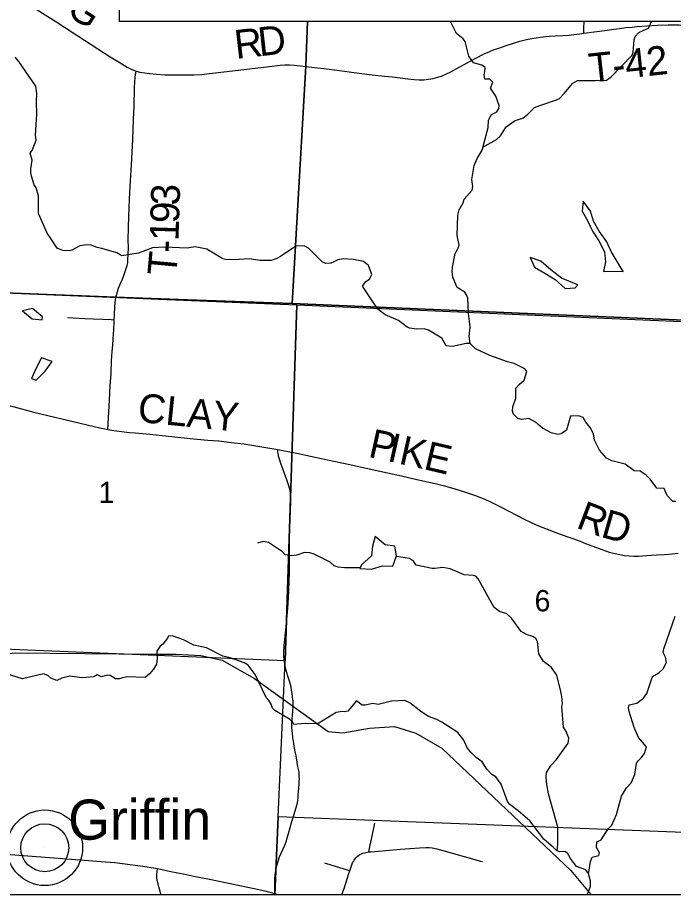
# Model space of a CAD drawing. Extents: x 0 to 34, y 0 to 22.
# Drawn here: x 4.911 to 6.203, y 14.1 to 15.827 of the extents above; entities that cross this region are included whole.
import ezdxf

# ---------------------------------------------------------------- set-up
doc = ezdxf.new("R2010")
doc.units = 0
for name, color, linetype in [('Default', 7, 'Continuous'), ('GM_X_County_Road', 7, 'Continuous'), ('GM_X_County_Road_Text', 7, 'Continuous'), ('GM_X_Minor_Lake', 7, 'Continuous'), ('GM_X_Minor_River', 7, 'Continuous'), ('GM_X_Rail_Line', 7, 'Continuous'), ('GM_X_Section', 7, 'Continuous'), ('GM_X_Section_Text', 7, 'Continuous'), ('GM_X_State_Route', 7, 'Continuous'), ('GM_X_Township_Road', 7, 'Continuous'), ('GM_X_Township_Road_Text', 7, 'Continuous'), ('GM_X_Unincorporated', 7, 'Continuous'), ('GM_X_Unincorporated_Location', 7, 'Continuous'), ('GM_X_Unincorporated_Text', 7, 'Continuous'), ('SH_Data', 7, 'Continuous')]:
    doc.layers.add(name, color=color, linetype=linetype)

msp = doc.modelspace()

# ---------------------------------------------------------------- linework, layer by layer
at = {"layer": 'Default'}
msp.add_lwpolyline([(5.112, 16.1987), (6.6303, 16.1987), (6.6303, 15.8189), (5.112, 15.8189)], close=True, dxfattribs=at)
at = {"layer": 'GM_X_County_Road'}
msp.add_line((5.4173, 14.1), (5.4174, 14.1019), dxfattribs=at)
for points in [[(4.9482, 15.8434), (4.9887, 15.8174), (5.0038, 15.808), (5.019, 15.7979), (5.0432, 15.782), (5.0691, 15.765), (5.0933, 15.7496), (5.1112, 15.7388), (5.1271, 15.7288), (5.1365, 15.7241), (5.1416, 15.7224), (5.1447, 15.7214)], [(6.0265, 15.7958), (6.0265, 15.806), (6.0268, 15.8189)], [(5.4792, 15.7304), (5.4958, 15.7284), (5.5019, 15.7276), (5.5142, 15.7261), (5.5449, 15.7225), (5.5786, 15.718), (5.6093, 15.7142), (5.6339, 15.7114), (5.6493, 15.7097), (5.68, 15.7058), (5.6924, 15.7046), (5.7017, 15.7041), (5.711, 15.7043), (5.7203, 15.7053), (5.7295, 15.707), (5.7386, 15.7092), (5.7474, 15.7121), (5.756, 15.7156), (5.7644, 15.7198), (5.7806, 15.729), (5.8134, 15.7465), (5.83, 15.755), (5.8412, 15.7601), (5.8498, 15.7636), (5.8586, 15.7667), (5.8732, 15.7715), (5.8879, 15.7761), (5.9, 15.7799), (5.9132, 15.7832), (5.9235, 15.7854), (5.9321, 15.7869), (5.941, 15.7881), (5.9515, 15.7895), (5.9577, 15.7902), (5.9698, 15.7908), (5.9849, 15.7915), (5.9973, 15.7922), (6.0066, 15.7932), (6.0184, 15.7945), (6.0265, 15.7958)], [(5.1447, 15.7214), (5.1521, 15.7195), (5.162, 15.7179), (5.1708, 15.7168), (5.1846, 15.7152), (5.2013, 15.7141), (5.2178, 15.7136), (5.2399, 15.7138), (5.2585, 15.7141), (5.274, 15.7148), (5.2895, 15.7163), (5.3172, 15.7197), (5.3789, 15.7268), (5.4066, 15.7303), (5.4281, 15.7329), (5.4374, 15.7335), (5.4466, 15.7335), (5.4558, 15.733), (5.4681, 15.7318), (5.4792, 15.7304)], [(4.878, 15.0668), (4.9044, 15.0599), (4.9435, 15.0498), (4.9706, 15.0431), (5.0099, 15.0338), (5.0734, 15.019), (5.0828, 15.017), (5.0888, 15.0157)], [(5.0888, 15.0157), (5.1008, 15.0138), (5.1319, 15.0098), (5.1428, 15.0087), (5.1717, 15.0062), (5.1902, 15.0046), (5.2211, 15.0014), (5.2511, 14.9979), (5.2859, 14.9946), (5.3066, 14.9929)], [(5.3066, 14.9929), (5.3076, 14.9929), (5.3323, 14.9902), (5.3569, 14.9871), (5.3845, 14.983), (5.4121, 14.9784), (5.4235, 14.9763)], [(5.4174, 14.1019), (5.4175, 14.1033), (5.418, 14.1303), (5.4185, 14.1381), (5.4197, 14.1469), (5.4217, 14.1562), (5.4242, 14.1653), (5.4273, 14.1741), (5.4309, 14.1827), (5.4372, 14.1969), (5.4405, 14.2055), (5.4424, 14.2113), (5.4448, 14.2201), (5.4478, 14.2319), (5.4512, 14.2435), (5.456, 14.2578), (5.4592, 14.2694), (5.4619, 14.2779), (5.463, 14.2841), (5.4637, 14.2908), (5.464, 14.2958), (5.4642, 14.3025), (5.4648, 14.3096), (5.4655, 14.3168), (5.466, 14.3232), (5.4662, 14.3277), (5.466, 14.3322), (5.4654, 14.341), (5.4641, 14.3465), (5.4635, 14.3491), (5.4629, 14.3518), (5.4617, 14.3606), (5.4595, 14.3729), (5.4573, 14.3843), (5.4552, 14.3969), (5.4534, 14.4091), (5.4525, 14.4177), (5.4514, 14.4273), (5.4516, 14.4371), (5.4526, 14.4525), (5.4532, 14.4617), (5.4537, 14.4704), (5.4537, 14.4749), (5.4537, 14.4814), (5.4534, 14.4834), (5.4517, 14.4956), (5.4509, 14.502), (5.4498, 14.5081), (5.4491, 14.5112), (5.4467, 14.52), (5.4449, 14.5259), (5.443, 14.5318), (5.4421, 14.5347), (5.4404, 14.5407), (5.4382, 14.5497), (5.4366, 14.5589), (5.4358, 14.5682), (5.4357, 14.5775), (5.4363, 14.5899), (5.4374, 14.6023), (5.44, 14.627), (5.4409, 14.6362), (5.4421, 14.6484), (5.4433, 14.6636), (5.4438, 14.6728), (5.4451, 14.6975), (5.4463, 14.7192), (5.4468, 14.7316), (5.447, 14.7409), (5.4466, 14.7718), (5.4465, 14.7843), (5.4465, 14.7936), (5.4467, 14.806), (5.447, 14.8214), (5.4474, 14.8338), (5.4484, 14.8525), (5.4495, 14.8772), (5.4494, 14.8834), (5.4488, 14.8895), (5.4478, 14.8955), (5.4455, 14.9045), (5.4416, 14.9162), (5.4298, 14.9483), (5.4269, 14.9572), (5.4253, 14.9632), (5.4248, 14.9654), (5.4242, 14.9683), (5.4238, 14.9708), (5.4235, 14.9763)], [(5.4235, 14.9763), (5.4335, 14.9745), (5.4609, 14.9687), (5.4791, 14.9648), (5.5215, 14.9558), (5.5655, 14.9465), (5.6033, 14.9379), (5.6246, 14.9335), (5.6397, 14.9302), (5.667, 14.9241), (5.6972, 14.9173), (5.7335, 14.9091), (5.7516, 14.9046), (5.7725, 14.8988), (5.7933, 14.8922), (5.8109, 14.886), (5.8312, 14.8781), (5.8425, 14.8731), (5.8649, 14.8621), (5.9089, 14.839), (5.9227, 14.8321), (5.9369, 14.8259), (5.9542, 14.819), (5.9774, 14.8103), (6.0008, 14.8021), (6.0155, 14.797), (6.0298, 14.7912), (6.0442, 14.7855), (6.0617, 14.7791), (6.0763, 14.7743), (6.0882, 14.7711), (6.0972, 14.7691), (6.1063, 14.7676), (6.1154, 14.7666), (6.1247, 14.7661), (6.1339, 14.7662), (6.1495, 14.7673), (6.1693, 14.7688), (6.1848, 14.7695), (6.2, 14.7704), (6.212, 14.7717)]]:
    msp.add_lwpolyline(points, dxfattribs=at)
at = {"layer": 'GM_X_Minor_Lake'}
for points in [[(6.1036, 15.3264), (6.0918, 15.3462), (6.0801, 15.3663), (6.0714, 15.3853), (6.0563, 15.4061), (6.0453, 15.4255), (6.0392, 15.4452), (6.0249, 15.4654), (6.0226, 15.4452), (6.0339, 15.4255), (6.043, 15.4061), (6.0559, 15.3872), (6.0669, 15.3655), (6.0691, 15.3454), (6.065, 15.3264)], [(6.1036, 15.3264), (6.0918, 15.3462), (6.0801, 15.3663), (6.0714, 15.3853), (6.0563, 15.4061), (6.0453, 15.4255), (6.0392, 15.4452), (6.0249, 15.4654), (6.0226, 15.4452), (6.0339, 15.4255), (6.043, 15.4061), (6.0559, 15.3872), (6.0669, 15.3655), (6.0691, 15.3454), (6.065, 15.3264), (6.0847, 15.3272), (6.1036, 15.3264), (6.1036, 15.3279)], [(6.0147, 15.3002), (5.9821, 15.3135), (5.9609, 15.3298), (5.9413, 15.3469), (5.9204, 15.3541), (5.9292, 15.3352)], [(6.0147, 15.3002), (5.9821, 15.3135), (5.9609, 15.3298), (5.9413, 15.3469), (5.9204, 15.3541), (5.9292, 15.3352), (5.9496, 15.3234), (5.97, 15.3109), (5.9897, 15.2934), (6.009, 15.2945), (6.0147, 15.3002)], [(5.9292, 15.3352), (5.9496, 15.3234), (5.97, 15.3109), (5.9897, 15.2934), (6.009, 15.2945), (6.0147, 15.3002)], [(6.065, 15.3264), (6.0847, 15.3272), (6.1036, 15.3264)], [(4.9603, 15.2375), (4.9409, 15.2535), (4.9208, 15.249), (4.9401, 15.2334), (4.9594, 15.2315)], [(4.9606, 15.2372), (4.9409, 15.2535), (4.9208, 15.249), (4.9401, 15.2334), (4.9594, 15.2315), (4.9602, 15.2368)], [(4.9594, 15.2315), (4.9603, 15.2375)], [(4.9587, 15.1564), (4.9473, 15.1351), (4.939, 15.1158), (4.9481, 15.1127)], [(4.9481, 15.1127), (4.9655, 15.1302), (4.9791, 15.1495), (4.9587, 15.1564), (4.9473, 15.1351), (4.939, 15.1158), (4.9481, 15.1127)], [(4.9481, 15.1127), (4.9655, 15.1302), (4.9791, 15.1495), (4.9587, 15.1564)], [(5.6541, 14.7856), (5.6348, 14.7886), (5.6152, 14.8049), (5.6103, 14.7856), (5.608, 14.7666), (5.5883, 14.7491), (5.5849, 14.7419)], [(5.5849, 14.7419), (5.6084, 14.7404), (5.6299, 14.7468), (5.6504, 14.7465), (5.6575, 14.7666), (5.6541, 14.7856), (5.6348, 14.7886), (5.6152, 14.8049), (5.6103, 14.7856), (5.608, 14.7666), (5.5883, 14.7491), (5.5849, 14.7419)], [(5.5849, 14.7419), (5.6084, 14.7404), (5.6299, 14.7468), (5.6504, 14.7465), (5.6575, 14.7666), (5.6541, 14.7856)]]:
    msp.add_lwpolyline(points, dxfattribs=at)
at = {"layer": 'GM_X_Minor_River'}
for points in [[(5.8027, 15.1852), (5.8003, 15.1992), (5.8025, 15.217), (5.7993, 15.2448), (5.7981, 15.2744), (5.7961, 15.2797), (5.7919, 15.2861), (5.7771, 15.2951), (5.7683, 15.3152), (5.7672, 15.3259), (5.7675, 15.3353), (5.773, 15.3623), (5.7783, 15.3711), (5.7805, 15.3787), (5.777, 15.3977), (5.7783, 15.4379), (5.7809, 15.4478), (5.7888, 15.4619), (5.7903, 15.4688), (5.8064, 15.4871), (5.8079, 15.4939), (5.8059, 15.508), (5.81, 15.5357), (5.8159, 15.549), (5.8257, 15.5654), (5.8376, 15.6103), (5.8382, 15.6247), (5.8442, 15.6361), (5.8548, 15.6411), (5.8589, 15.6476), (5.8597, 15.6533), (5.8531, 15.6719), (5.8425, 15.6878), (5.8473, 15.6992), (5.8409, 15.7052), (5.8314, 15.7052), (5.8302, 15.7143), (5.8313, 15.7196), (5.8317, 15.7284), (5.8256, 15.7329), (5.8089, 15.7377), (5.7998, 15.7506), (5.7924, 15.7798), (5.7883, 15.7851), (5.7757, 15.7956), (5.7681, 15.81), (5.7637, 15.8189)], [(5.8274, 15.5717), (5.854, 15.5868), (5.8619, 15.5937), (5.8735, 15.6112), (5.8912, 15.6239), (5.9059, 15.6289), (5.9161, 15.6362), (5.9289, 15.6495), (5.9395, 15.6538), (5.9727, 15.6646), (5.978, 15.6676), (5.9878, 15.6772), (6.0047, 15.6978), (6.0138, 15.7028), (6.0489, 15.703), (6.0538, 15.7034), (6.0603, 15.7023), (6.0709, 15.7031), (6.0795, 15.7092), (6.1213, 15.7527), (6.1235, 15.7588), (6.1253, 15.7831), (6.1275, 15.7896), (6.1347, 15.7976), (6.143, 15.8011), (6.1532, 15.8057), (6.1594, 15.8189)], [(5.8027, 15.1852), (5.7944, 15.1851), (5.7675, 15.1789), (5.7554, 15.1803), (5.7463, 15.1951), (5.7201, 15.2109), (5.7121, 15.2135), (5.6959, 15.2131), (5.6834, 15.2149), (5.6781, 15.2171), (5.6613, 15.2303), (5.6348, 15.2416), (5.6208, 15.2525), (5.5906, 15.2975), (5.597, 15.3067), (5.6042, 15.3117), (5.6087, 15.3208), (5.6022, 15.3386), (5.5927, 15.3466), (5.573, 15.3502), (5.5525, 15.3513), (5.542, 15.3497), (5.5337, 15.3459), (5.528, 15.3428), (5.5174, 15.3423), (5.5113, 15.3454), (5.484, 15.3729), (5.4756, 15.3771), (5.459, 15.3766), (5.4288, 15.3563), (5.4216, 15.3521), (5.4103, 15.3482), (5.3884, 15.3481), (5.3679, 15.3514), (5.3373, 15.3497), (5.3207, 15.3504), (5.3157, 15.3519), (5.2839, 15.3707), (5.2611, 15.3751), (5.2453, 15.3728), (5.2006, 15.3748), (5.1768, 15.3732), (5.1492, 15.3627), (5.1163, 15.3573), (5.1069, 15.3637), (5.0769, 15.3718), (5.0682, 15.3741), (5.0561, 15.3786), (5.0478, 15.3793), (5.0342, 15.3773), (5.0179, 15.3685), (5.0126, 15.3673), (5.0005, 15.368), (4.9892, 15.3725), (4.9766, 15.3918), (4.9693, 15.402), (4.9525, 15.441), (4.9523, 15.4756), (4.9477, 15.4915), (4.9443, 15.4972), (4.9385, 15.5146), (4.9377, 15.5215), (4.9373, 15.5291), (4.9399, 15.5458), (4.9364, 15.5594), (4.9401, 15.5651), (4.9476, 15.5853), (4.9468, 15.5952), (4.9492, 15.6362), (4.9483, 15.6613), (4.9494, 15.6772), (4.9471, 15.6916), (4.9139, 15.7404), (4.9063, 15.7487)], [(6.2072, 14.874), (6.2015, 14.874), (6.1905, 14.8853), (6.1843, 14.8993), (6.1699, 14.9), (6.1566, 14.9178), (6.149, 14.9254), (6.1372, 14.9333), (6.1255, 14.9343), (6.1077, 14.9472), (6.0812, 14.9539), (6.0709, 14.9591), (6.0568, 14.975), (6.0469, 14.9947), (6.0449, 15.0072), (6.0388, 15.0197), (6.0304, 15.0299), (6.0251, 15.0394), (6.0156, 15.0424), (5.9997, 15.0419), (5.9923, 15.0145), (5.9814, 15.0072), (5.9753, 15.0057), (5.9621, 15.009), (5.9545, 15.0128), (5.945, 15.0184), (5.931, 15.0301), (5.9177, 15.0373), (5.9033, 15.0353), (5.8961, 15.0375), (5.8878, 15.0455), (5.8855, 15.0515), (5.8865, 15.0603), (5.8921, 15.077), (5.8924, 15.0968), (5.8992, 15.1044), (5.9086, 15.1124), (5.9142, 15.1295), (5.91, 15.1348), (5.8888, 15.1457), (5.8759, 15.1487), (5.8414, 15.1611), (5.8126, 15.1746), (5.8027, 15.1852)], [(5.5854, 14.743), (5.5549, 14.7429), (5.5428, 14.7444), (5.5345, 14.7474), (5.5269, 14.7546), (5.4954, 14.7703), (5.4867, 14.7729), (5.4764, 14.7733), (5.461, 14.7679), (5.4508, 14.7667), (5.4379, 14.7689), (5.4326, 14.7749), (5.4056, 14.793), (5.395, 14.7952), (5.384, 14.7918)], [(5.9735, 14.1862), (5.9749, 14.1992), (5.9748, 14.2322), (5.9563, 14.2978), (5.9531, 14.3168), (5.9519, 14.3304), (5.953, 14.3403), (5.9617, 14.3544), (5.9722, 14.3655), (5.9955, 14.3979), (5.9966, 14.4074), (5.9916, 14.421), (5.9859, 14.4297), (5.9826, 14.4703), (5.9845, 14.4753), (5.9829, 14.4897), (5.981, 14.4999), (5.9732, 14.5318), (5.9622, 14.5477), (5.947, 14.559), (5.9378, 14.5741), (5.9347, 14.598), (5.9316, 14.6041), (5.9259, 14.6082), (5.9131, 14.6119), (5.9028, 14.618), (5.8841, 14.6441), (5.8743, 14.6528), (5.8599, 14.6572), (5.8496, 14.6652), (5.8408, 14.6803), (5.824, 14.711), (5.8183, 14.7212), (5.8134, 14.7265), (5.8081, 14.7283), (5.7906, 14.7294), (5.763, 14.7414), (5.7486, 14.7436), (5.7327, 14.7416), (5.7274, 14.7416), (5.696, 14.7482), (5.691, 14.7562), (5.683, 14.7615), (5.6571, 14.7653)], [(6.0342, 14.1428), (6.0361, 14.1441), (6.039, 14.165), (6.0424, 14.1737), (6.056, 14.1764), (6.0571, 14.1821), (6.051, 14.1924), (6.0521, 14.2038), (6.06, 14.2072), (6.0739, 14.2293), (6.081, 14.2362), (6.0908, 14.2575), (6.1004, 14.2932), (6.1105, 14.31), (6.1192, 14.3199), (6.1263, 14.3363), (6.13, 14.3587), (6.1341, 14.3637), (6.139, 14.369), (6.1458, 14.3774), (6.1495, 14.3907), (6.1339, 14.4088), (6.1251, 14.4285), (6.1155, 14.4604), (6.1143, 14.4676), (6.1154, 14.4733), (6.1305, 14.4768), (6.1437, 14.4867), (6.1505, 14.4955), (6.1613, 14.529), (6.1737, 14.5363), (6.1824, 14.5443), (6.1891, 14.5565), (6.1868, 14.5671), (6.1822, 14.5766), (6.1837, 14.5834), (6.2057, 14.6477)], [(6.0329, 14.1), (6.0348, 14.1038), (6.0393, 14.116), (6.0396, 14.1259), (6.0354, 14.141), (6.0304, 14.1486), (6.0118, 14.1553), (5.9997, 14.1708), (5.9943, 14.1811), (5.989, 14.1848), (5.9784, 14.1836), (5.9727, 14.1866), (5.9663, 14.1927), (5.9473, 14.2089), (5.9198, 14.2452), (5.897, 14.2648), (5.8803, 14.2769), (5.8758, 14.2833), (5.8635, 14.3174), (5.8532, 14.3314), (5.8449, 14.3363), (5.8353, 14.3469), (5.8262, 14.3613), (5.8144, 14.3695), (5.8034, 14.3801), (5.7966, 14.3884), (5.79, 14.4036), (5.7782, 14.4191), (5.7464, 14.4394), (5.7365, 14.4447), (5.7206, 14.4503), (5.7054, 14.4605), (5.6837, 14.4771), (5.6735, 14.4816), (5.6474, 14.4803), (5.6213, 14.4741), (5.6107, 14.4759), (5.5956, 14.4728), (5.5896, 14.4728), (5.5789, 14.4811), (5.5613, 14.4612), (5.5556, 14.4593), (5.5503, 14.46), (5.5386, 14.4581), (5.5046, 14.4374), (5.4993, 14.4362), (5.4774, 14.4369), (5.4555, 14.4348), (5.4528, 14.4398), (5.4467, 14.4454), (5.4179, 14.462), (5.4129, 14.4669), (5.4103, 14.4748), (5.4057, 14.482), (5.4007, 14.4877), (5.3793, 14.5328), (5.3652, 14.5513), (5.3573, 14.5558), (5.3296, 14.5659), (5.3156, 14.5693), (5.2833, 14.5858), (5.2583, 14.591), (5.2382, 14.6011), (5.2174, 14.6086), (5.2083, 14.6093), (5.2068, 14.6044), (5.1974, 14.5925), (5.1922, 14.5891), (5.1858, 14.5792), (5.1862, 14.5655), (5.1848, 14.5537), (5.1792, 14.5438), (5.1713, 14.5343), (5.1626, 14.527), (5.1263, 14.5288), (5.118, 14.5264), (5.1119, 14.5245), (5.104, 14.5248), (5.0937, 14.5309), (5.0884, 14.5316), (5.076, 14.5285), (5.068, 14.5322), (5.0612, 14.5284), (5.0381, 14.5268), (5.0143, 14.5297), (4.9984, 14.5262), (4.9886, 14.5216), (4.9769, 14.526), (4.9712, 14.531), (4.9621, 14.5347), (4.9209, 14.5246), (4.8898, 14.5347)]]:
    msp.add_lwpolyline(points, dxfattribs=at)
at = {"layer": 'GM_X_Rail_Line'}
for points in [[(2.1, 18.4819), (2.1, 15.4153), (3.9123, 15.3323), (3.9451, 15.3313), (3.973, 15.329), (4.0133, 15.3262), (4.0257, 15.3251), (4.0381, 15.324), (4.0782, 15.3206), (4.1061, 15.3185), (4.1743, 15.3141), (4.1849, 15.3132), (4.1956, 15.3121), (4.1973, 15.3118), (5.1044, 15.2759), (5.2458, 15.271), (5.4522, 15.2638), (5.479, 15.731), (5.4821, 15.8189)], [(5.4821, 15.8189), (5.479, 15.731), (5.4522, 15.2638), (6.2705, 15.2288), (6.4764, 15.22), (8.4272, 15.1429)], [(4.1532, 14.3849), (4.2282, 14.4236), (4.3306, 14.4812), (4.4305, 14.5219), (4.5308, 14.5414), (4.648, 14.5518), (4.9079, 14.5757), (5.1792, 14.5733), (5.2237, 14.5733), (5.272, 14.5707), (5.3144, 14.561), (5.3776, 14.525), (5.5225, 14.4206), (5.5518, 14.4183), (5.6045, 14.4272), (5.6536, 14.4306), (5.6957, 14.4175), (5.7467, 14.3883), (6.0004, 14.1469), (6.0402, 14.1)]]:
    msp.add_lwpolyline(points, dxfattribs=at)
msp.add_lwpolyline([(2.1, 15.4153), (2.1, 14.1), (6.4223, 14.1), (6.4607, 14.8895), (6.4764, 15.22), (6.2705, 15.2288), (5.4522, 15.2638), (5.2458, 15.271), (5.1044, 15.2759), (4.1973, 15.3118), (4.1956, 15.3121), (4.1849, 15.3132), (4.1743, 15.3141), (4.1061, 15.3185), (4.0782, 15.3206), (4.0381, 15.324), (4.0257, 15.3251), (4.0133, 15.3262), (3.973, 15.329), (3.9451, 15.3313), (3.9123, 15.3323)], close=True, dxfattribs=at)
at = {"layer": 'GM_X_Section'}
for points in [[(5.4613, 15.2612), (5.438, 14.5597), (4.7084, 14.5904), (4.7434, 15.2908)], [(6.4755, 15.2172), (6.4272, 14.2142), (5.4247, 14.2527), (5.438, 14.5597), (5.4613, 15.2612)]]:
    msp.add_lwpolyline(points, close=True, dxfattribs=at)
at = {"layer": 'GM_X_State_Route'}
for points in [[(4.8801, 14.1799), (5.0254, 14.1687), (5.0841, 14.1645), (5.1027, 14.1629), (5.1181, 14.161), (5.1581, 14.1554), (5.1826, 14.1517), (5.187, 14.1508), (5.213, 14.1454), (5.2404, 14.14), (5.2586, 14.1362), (5.289, 14.1298), (5.3772, 14.1115), (5.3984, 14.1068), (5.4174, 14.1019)], [(5.4174, 14.1019), (5.4225, 14.1006), (5.4249, 14.1)]]:
    msp.add_lwpolyline(points, dxfattribs=at)
at = {"layer": 'GM_X_Township_Road'}
for points in [[(6.0265, 15.7958), (6.0466, 15.7984), (6.072, 15.8019), (6.0843, 15.8036), (6.0965, 15.8054), (6.1088, 15.807), (6.1211, 15.808), (6.1303, 15.809), (6.151, 15.8106), (6.1715, 15.8118), (6.1922, 15.8123), (6.2136, 15.8121), (6.23, 15.8111), (6.2465, 15.8096), (6.2599, 15.8077), (6.2905, 15.8036), (6.3057, 15.8011), (6.3269, 15.7969), (6.345, 15.7931), (6.354, 15.7915), (6.3568, 15.7911), (6.3596, 15.7909), (6.3626, 15.7913)], [(5.1046, 15.2754), (5.1058, 15.2802), (5.1081, 15.2869), (5.1103, 15.294), (5.1134, 15.3019), (5.1176, 15.3115), (5.1209, 15.3208), (5.1245, 15.3306), (5.127, 15.3388), (5.1283, 15.344), (5.1287, 15.3504), (5.129, 15.3604), (5.1295, 15.374), (5.1293, 15.3886), (5.13, 15.4134), (5.1306, 15.4351), (5.1316, 15.4691), (5.1327, 15.4938), (5.1341, 15.5158), (5.1355, 15.537), (5.138, 15.5866), (5.1398, 15.6268), (5.1406, 15.6516), (5.1414, 15.6889), (5.1427, 15.7102), (5.1447, 15.7214)], [(5.1014, 15.2317), (5.1019, 15.2406), (5.1031, 15.2583), (5.1041, 15.2711), (5.1046, 15.2754)], [(5.0099, 15.2364), (5.0209, 15.2354), (5.044, 15.234), (5.0953, 15.232), (5.1014, 15.2317)], [(5.0888, 15.0157), (5.0923, 15.0734), (5.0939, 15.1012), (5.0953, 15.126), (5.0964, 15.1508), (5.0976, 15.1694), (5.0987, 15.1817), (5.0997, 15.1941), (5.1007, 15.2127), (5.1013, 15.2283), (5.1014, 15.2317)], [(5.6032, 14.1836), (5.6043, 14.1904), (5.6053, 14.1967), (5.6079, 14.2091), (5.6126, 14.2308), (5.6144, 14.2401)], [(5.5655, 14.1467), (5.5687, 14.1561), (5.571, 14.162), (5.5724, 14.1648), (5.574, 14.1676), (5.5758, 14.1702), (5.5777, 14.1727), (5.58, 14.175), (5.5826, 14.177), (5.5853, 14.1787), (5.5882, 14.1801), (5.5911, 14.1813), (5.5942, 14.1822), (5.5973, 14.1828), (5.6032, 14.1836)], [(5.6032, 14.1836), (5.6066, 14.184), (5.6221, 14.1853), (5.6654, 14.189), (5.6839, 14.1906), (5.7026, 14.1921), (5.7151, 14.1926), (5.7214, 14.1924), (5.7276, 14.1917), (5.7368, 14.1899), (5.7489, 14.1867), (5.7908, 14.1745), (5.8118, 14.1686), (5.8223, 14.1654), (5.8268, 14.1648)], [(5.5159, 14.1622), (5.5303, 14.1575), (5.5452, 14.1529), (5.5601, 14.1484), (5.5655, 14.1467)], [(5.1935, 14.1), (5.1935, 14.1003), (5.1922, 14.1064), (5.1896, 14.1153), (5.1878, 14.1212), (5.1864, 14.1273), (5.1856, 14.1335), (5.1856, 14.1396), (5.1861, 14.1439), (5.187, 14.1508)], [(5.55, 14.1), (5.5542, 14.1119), (5.5637, 14.1413), (5.5655, 14.1467)]]:
    msp.add_lwpolyline(points, dxfattribs=at)
at = {"layer": 'GM_X_Unincorporated'}
for radius in [0.0744, 0.0472]:
    msp.add_circle((4.9649, 14.1919), radius, dxfattribs=at)
at = {"layer": 'GM_X_Unincorporated_Location'}
msp.add_line((4.9649, 14.1919), (4.9649, 14.1919), dxfattribs=at)
at = {"layer": 'GM_X_Unincorporated_Text'}
for points in [[(4.6857, 14.1), (5.4179, 14.1), (5.4247, 14.2527), (5.438, 14.5597), (4.7084, 14.5904)], [(5.4179, 14.1), (6.4225, 14.1), (6.4272, 14.2142), (5.4247, 14.2527)]]:
    msp.add_lwpolyline(points, close=True, dxfattribs=at)
at = {"layer": 'SH_Data'}
msp.add_line((2.1, 14.1), (8.9, 14.1), dxfattribs=at)

# ---------------------------------------------------------------- texts
at = {"layer": 'GM_X_County_Road_Text'}
for s, height, rotation, p in [('G', 0.0568, 327.188, (5.0047, 15.8339)), ('R', 0.0568, 6.6109, (5.3415, 15.745)), ('D', 0.0568, 6.3076, (5.3877, 15.7504)), ('CLAY', 0.05682, 354.2631, (5.1463, 15.0309)), ('P', 0.0568, 347.4367, (5.5999, 14.9621)), ('I', 0.0568, 347.4331, (5.6373, 14.9538)), ('K', 0.0568, 347.419, (5.6601, 14.9487)), ('E', 0.0568, 346.7558, (5.7087, 14.9379)), ('R', 0.0568, 339.2133, (6.0089, 14.8228)), ('D', 0.0568, 343.9988, (6.0574, 14.8047))]:
    msp.add_text(s, height=height, rotation=rotation, dxfattribs=at).set_placement(p)
at = {"layer": 'GM_X_Section_Text'}
for s, p in [('1', (5.0709, 14.8708)), ('6', (5.9292, 14.6575))]:
    msp.add_text(s, height=0.0419, rotation=0, dxfattribs=at).set_placement(p)
at = {"layer": 'GM_X_Township_Road_Text'}
for s, height, rotation, p in [('T-42', 0.05682, 6.2262, (6.039, 15.699)), ('3', 0.0568, 87.8086, (5.2301, 15.456)), ('9', 0.0568, 88.3032, (5.2291, 15.4212)), ('1', 0.0568, 88.3325, (5.2281, 15.3862)), ('-', 0.0568, 88.2971, (5.2274, 15.3628)), ('T', 0.0568, 84.7427, (5.2233, 15.3167))]:
    msp.add_text(s, height=height, rotation=rotation, dxfattribs=at).set_placement(p)
at = {"layer": 'GM_X_Unincorporated_Text'}
msp.add_text('Griffin', height=0.07898, rotation=0, dxfattribs=at).set_placement((5.0109, 14.2078))

doc.saveas('drawing.dxf')
